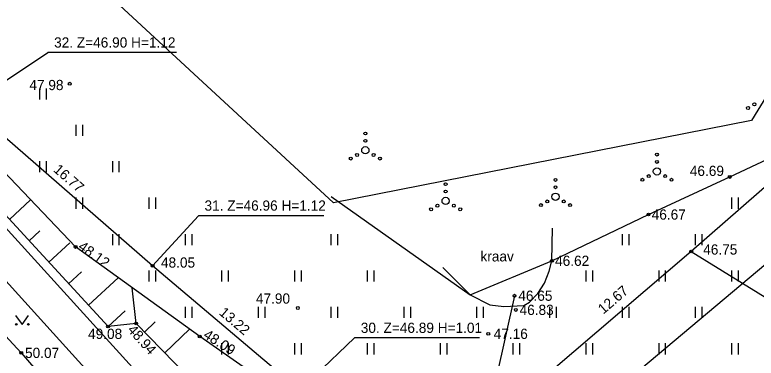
# Model space of a CAD drawing. Extents: x 642747 to 644424, y 6457048 to 6458238.
# Drawn here: x 644020.1 to 644071, y 6457560 to 6457583.6 of the extents above; entities that cross this region are included whole.
import ezdxf

# ---------------------------------------------------------------- set-up
doc = ezdxf.new("R2010")
doc.units = 0
for name, color, linetype in [('DTRASS', 7, 'Continuous'), ('HALJASTUS', 7, 'Continuous'), ('JOONSIDE', 7, 'Continuous'), ('KOORDPUNKT', 7, 'Continuous'), ('KORGUS', 7, 'Continuous'), ('KPKAABEL', 7, 'Continuous'), ('MOOTPIIR', 7, 'Continuous'), ('RELJEEF', 7, 'Continuous'), ('TEE', 7, 'Continuous'), ('VEEKOGU', 7, 'Continuous')]:
    doc.layers.add(name, color=color, linetype=linetype)

msp = doc.modelspace()

# ---------------------------------------------------------------- linework, layer by layer
at = {"layer": 'DTRASS'}
msp.add_lwpolyline([(644054.394, 6457564.336), (644048.175, 6457536.442)], dxfattribs=at)
at = {"layer": 'HALJASTUS'}
for p, q in [((644021.79, 6457578.569), (644021.79, 6457577.807)), ((644022.245, 6457578.569), (644022.245, 6457577.807)), ((644024.29, 6457576.069), (644024.29, 6457575.307)), ((644024.745, 6457576.069), (644024.745, 6457575.307)), ((644021.79, 6457573.569), (644021.79, 6457572.807)), ((644022.245, 6457573.569), (644022.245, 6457572.807)), ((644026.79, 6457573.569), (644026.79, 6457572.807)), ((644027.245, 6457573.569), (644027.245, 6457572.807)), ((644024.29, 6457571.069), (644024.29, 6457570.307)), ((644024.745, 6457571.069), (644024.745, 6457570.307)), ((644029.29, 6457571.069), (644029.29, 6457570.307)), ((644029.745, 6457571.069), (644029.745, 6457570.307)), ((644069.29, 6457571.069), (644069.29, 6457570.307)), ((644069.745, 6457571.069), (644069.745, 6457570.307)), ((644026.79, 6457568.569), (644026.79, 6457567.807)), ((644027.245, 6457568.569), (644027.245, 6457567.807)), ((644031.79, 6457568.569), (644031.79, 6457567.807)), ((644032.245, 6457568.569), (644032.245, 6457567.807)), ((644041.79, 6457568.569), (644041.79, 6457567.807)), ((644042.245, 6457568.569), (644042.245, 6457567.807)), ((644061.79, 6457568.569), (644061.79, 6457567.807)), ((644062.245, 6457568.569), (644062.245, 6457567.807)), ((644066.79, 6457568.569), (644066.79, 6457567.807)), ((644067.245, 6457568.569), (644067.245, 6457567.807)), ((644029.29, 6457566.069), (644029.29, 6457565.307)), ((644029.745, 6457566.069), (644029.745, 6457565.307)), ((644034.29, 6457566.069), (644034.29, 6457565.307)), ((644034.745, 6457566.069), (644034.745, 6457565.307)), ((644039.29, 6457566.069), (644039.29, 6457565.307)), ((644039.745, 6457566.069), (644039.745, 6457565.307)), ((644044.29, 6457566.069), (644044.29, 6457565.307)), ((644044.745, 6457566.069), (644044.745, 6457565.307)), ((644059.29, 6457566.069), (644059.29, 6457565.307)), ((644059.745, 6457566.069), (644059.745, 6457565.307)), ((644064.29, 6457566.069), (644064.29, 6457565.307)), ((644064.745, 6457566.069), (644064.745, 6457565.307)), ((644069.29, 6457566.069), (644069.29, 6457565.307)), ((644069.745, 6457566.069), (644069.745, 6457565.307)), ((644031.79, 6457563.569), (644031.79, 6457562.807)), ((644032.245, 6457563.569), (644032.245, 6457562.807)), ((644036.79, 6457563.569), (644036.79, 6457562.807)), ((644037.245, 6457563.569), (644037.245, 6457562.807)), ((644041.79, 6457563.569), (644041.79, 6457562.807)), ((644042.245, 6457563.569), (644042.245, 6457562.807)), ((644046.79, 6457563.569), (644046.79, 6457562.807)), ((644047.245, 6457563.569), (644047.245, 6457562.807)), ((644051.79, 6457563.569), (644051.79, 6457562.807)), ((644052.245, 6457563.569), (644052.245, 6457562.807)), ((644056.79, 6457563.569), (644056.79, 6457562.807)), ((644057.245, 6457563.569), (644057.245, 6457562.807)), ((644061.79, 6457563.569), (644061.79, 6457562.807)), ((644062.245, 6457563.569), (644062.245, 6457562.807)), ((644066.79, 6457563.569), (644066.79, 6457562.807)), ((644067.245, 6457563.569), (644067.245, 6457562.807)), ((644020.133, 6457562.977), (644020.597, 6457562.37)), ((644020.597, 6457562.37), (644021.042, 6457562.977)), ((644034.29, 6457561.069), (644034.29, 6457560.307)), ((644034.745, 6457561.069), (644034.745, 6457560.307)), ((644039.29, 6457561.069), (644039.29, 6457560.307)), ((644039.745, 6457561.069), (644039.745, 6457560.307)), ((644044.29, 6457561.069), (644044.29, 6457560.307)), ((644044.745, 6457561.069), (644044.745, 6457560.307)), ((644049.29, 6457561.069), (644049.29, 6457560.307)), ((644049.745, 6457561.069), (644049.745, 6457560.307)), ((644054.29, 6457561.069), (644054.29, 6457560.307)), ((644054.745, 6457561.069), (644054.745, 6457560.307)), ((644059.29, 6457561.069), (644059.29, 6457560.307)), ((644059.745, 6457561.069), (644059.745, 6457560.307)), ((644064.29, 6457561.069), (644064.29, 6457560.307)), ((644064.745, 6457561.069), (644064.745, 6457560.307)), ((644069.29, 6457561.069), (644069.29, 6457560.307)), ((644069.745, 6457561.069), (644069.745, 6457560.307))]:
    msp.add_line(p, q, dxfattribs=at)
for points in [[(643947.897, 6457637.828), (643981.209, 6457604.157), (643998.602, 6457584.178), (644020.537, 6457560.412), (644029.925, 6457549.512)], [(644041.809, 6457571.148), (644051.359, 6457564.407), (644056.959, 6457566.734), (644063.59, 6457569.91), (644069.17, 6457572.488), (644076.19, 6457575.794), (644080.356, 6457579.056), (644082.641, 6457584.464), (644086.464, 6457590.743), (644093.515, 6457598.78), (644095.215, 6457603.14), (644095.047, 6457607.095)]]:
    msp.add_lwpolyline(points, dxfattribs=at)
for centre, radius in [((644070.857, 6457577.474), 0.1), ((644070.422, 6457577.224), 0.1), ((644044.155, 6457575.471), 0.1), ((644044.155, 6457574.971), 0.1), ((644044.155, 6457574.321), 0.25), ((644043.59, 6457573.996), 0.1), ((644044.72, 6457573.996), 0.1), ((644064.17, 6457574.021), 0.1), ((644043.155, 6457573.746), 0.1), ((644045.155, 6457573.746), 0.1), ((644064.17, 6457573.521), 0.1), ((644064.17, 6457572.871), 0.25), ((644057.208, 6457572.282), 0.1), ((644063.17, 6457572.296), 0.1), ((644063.605, 6457572.546), 0.1), ((644064.735, 6457572.546), 0.1), ((644065.17, 6457572.296), 0.1), ((644049.667, 6457571.992), 0.1), ((644057.208, 6457571.782), 0.1), ((644049.667, 6457571.492), 0.1), ((644057.208, 6457571.132), 0.25), ((644049.667, 6457570.842), 0.25), ((644056.643, 6457570.807), 0.1), ((644057.773, 6457570.807), 0.1), ((644048.667, 6457570.267), 0.1), ((644049.102, 6457570.517), 0.1), ((644050.232, 6457570.517), 0.1), ((644050.667, 6457570.267), 0.1), ((644056.208, 6457570.557), 0.1), ((644058.208, 6457570.557), 0.1), ((644020.196, 6457562.37), 0.055), ((644021.025, 6457562.37), 0.055)]:
    msp.add_circle(centre, radius, dxfattribs=at)
at = {"layer": 'KOORDPUNKT'}
for p, q in [((644016.901, 6457577.396), (644022.373, 6457581.022)), ((644031.192, 6457581.022), (644022.373, 6457581.022)), ((644029.553, 6457566.384), (644032.696, 6457569.824)), ((644041.306, 6457569.824), (644032.696, 6457569.824)), ((644066.524, 6457567.369), (644072.19, 6457563.871)), ((644039.639, 6457557.844), (644043.422, 6457561.433)), ((644051.996, 6457561.433), (644043.422, 6457561.433))]:
    msp.add_line(p, q, dxfattribs=at)
for points in [[(644066.524, 6457567.369), (644066.524, 6457567.369), (644066.524, 6457567.369)], [(644029.553, 6457566.384), (644029.553, 6457566.384), (644029.553, 6457566.384)]]:
    msp.add_lwpolyline(points, dxfattribs=at)
at = {"layer": 'KORGUS'}
for centre in [(644023.863, 6457578.887), (644069.17, 6457572.488), (644063.59, 6457569.91), (644024.267, 6457567.686), (644066.524, 6457567.369), (644056.959, 6457566.734), (644029.553, 6457566.384), (644054.394, 6457564.336), (644039.519, 6457563.493), (644054.482, 6457563.363), (644026.5, 6457562.219), (644028.426, 6457562.43), (644052.59, 6457561.721), (644032.787, 6457561.533), (644020.537, 6457560.412)]:
    msp.add_circle(centre, 0.1, dxfattribs=at)
at = {"layer": 'KPKAABEL'}
msp.add_lwpolyline([(644103.079, 6457652.715), (644111.131, 6457630.665), (644117.872, 6457612.305), (644117.831, 6457611.89), (644117.527, 6457611.592), (644112.751, 6457607.616), (644102.693, 6457600.124), (644092.698, 6457590.582), (644078.192, 6457577.561), (644066.524, 6457567.369), (644056.896, 6457559.139), (644048.865, 6457552.537), (644048.039, 6457551.927), (644047.155, 6457551.979), (644039.639, 6457557.844), (644029.553, 6457566.384), (644016.901, 6457577.396), (644002.145, 6457590.823), (643989.718, 6457602.415), (643976.894, 6457615.305), (643965.556, 6457626.702)], dxfattribs=at)
at = {"layer": 'MOOTPIIR'}
msp.add_lwpolyline([(643525.446, 6457467.559), (643537.447, 6457435.458), (643944.848, 6457628.51), (644046.626, 6457529.09), (644067.022, 6457529.09), (644138.408, 6457598.401), (644075.1, 6457775.215), (644046.02, 6457752.582), (644092.466, 6457611.94), (644070.657, 6457576.375), (644041.981, 6457570.717), (643942.223, 6457662.862)], close=True, dxfattribs=at)
at = {"layer": 'RELJEEF'}
for p, q in [((644019.726, 6457569.575), (644021.183, 6457570.917)), ((644021.081, 6457568.103), (644021.823, 6457568.787)), ((644022.436, 6457566.632), (644023.882, 6457567.964)), ((644023.791, 6457565.161), (644024.664, 6457565.965)), ((644025.146, 6457563.69), (644027.191, 6457565.574)), ((644028.426, 6457562.43), (644028.158, 6457564.876)), ((644026.5, 6457562.219), (644027.673, 6457563.299)), ((644029.003, 6457561.837), (644029.72, 6457562.534)), ((644030.398, 6457560.403), (644032.083, 6457562.042))]:
    msp.add_line(p, q, dxfattribs=at)
for points in [[(644040.652, 6457556.032), (644032.787, 6457561.533), (644024.267, 6457567.686), (644013.888, 6457578.559), (644004.095, 6457588.275), (643993.471, 6457598.922), (643984.908, 6457608.291), (643982.871, 6457611.083), (643985.277, 6457614.077)], [(644038.518, 6457554.209), (644034.582, 6457556.103), (644028.426, 6457562.43), (644026.5, 6457562.219), (644014.667, 6457575.068), (644002.176, 6457588.096), (643989.067, 6457601.802), (643980.842, 6457610.819), (643983.167, 6457613.454)]]:
    msp.add_lwpolyline(points, dxfattribs=at)
at = {"layer": 'TEE'}
for points in [[(644045.414, 6457537.961), (644044.12, 6457540.285), (644037.139, 6457549.214), (644032.867, 6457554.025), (644030.182, 6457557.185), (644018.058, 6457570.518), (644006.462, 6457582.723), (643994.161, 6457595.954), (643981.396, 6457609.563), (643968.526, 6457623.391), (643955.996, 6457636.272), (643954.769, 6457637.545)], [(643953.164, 6457635.53), (643954.521, 6457634.202), (643966.746, 6457621.258), (643979.497, 6457607.902), (643992.403, 6457593.942), (644004.789, 6457581.012), (644016.437, 6457568.699), (644028.361, 6457555.547), (644031.31, 6457552.113), (644035.03, 6457547.601), (644042.186, 6457538.294), (644042.986, 6457534.354), (644042.17, 6457531.304), (644041.041, 6457530.634)], [(644051.619, 6457549.694), (644075.076, 6457569.399), (644100.273, 6457592.468), (644111.741, 6457604.69), (644121.185, 6457609.883)]]:
    msp.add_lwpolyline(points, dxfattribs=at)
at = {"layer": 'VEEKOGU'}
for points in [[(644051.359, 6457564.407), (644052.694, 6457563.714), (644053.665, 6457563.59), (644055.044, 6457563.668), (644055.415, 6457563.901), (644055.986, 6457564.498), (644056.462, 6457565.204), (644056.764, 6457566.017), (644056.959, 6457566.734), (644056.998, 6457568.981)], [(644051.359, 6457564.407), (644049.478, 6457566.264)]]:
    msp.add_lwpolyline(points, dxfattribs=at)

# ---------------------------------------------------------------- texts
at = {"layer": 'JOONSIDE'}
for s, rotation, p in [('16.77', 318.9645, (644022.696, 6457572.906)), ('12.67', 40.5238, (644060.491, 6457563.037)), ('13.22', 319.7448, (644034.065, 6457563.088))]:
    msp.add_text(s, height=0.7, rotation=rotation, dxfattribs=at).set_placement(p)
at = {"layer": 'KOORDPUNKT'}
for s, p in [('32. Z=46.90 H=1.12', (644022.793, 6457581.372)), ('31. Z=46.96 H=1.12', (644033.116, 6457570.174)), ('30. Z=46.89 H=1.01', (644043.842, 6457561.783))]:
    msp.add_text(s, height=0.7, dxfattribs=at).set_placement(p)
at = {"layer": 'KORGUS'}
for s, p in [(' 47.98', (644020.834, 6457578.451)), ('46.69', (644066.428, 6457572.558)), ('46.67', (644063.811, 6457569.56)), ('46.75', (644067.346, 6457567.159)), ('48.05', (644030.128, 6457566.264)), ('46.62', (644057.18, 6457566.384)), (' 46.65', (644054.394, 6457563.986)), (' 47.90', (644036.384, 6457563.792)), (' 46.83', (644054.482, 6457563.013)), (' 49.08', (644024.863, 6457561.37)), ('47.16', (644052.965, 6457561.371)), (' 50.07', (644020.537, 6457560.062))]:
    msp.add_text(s, height=0.7, dxfattribs=at).set_placement(p)
for s, rotation, p in [(' 48.12', 324.1867, (644024.173, 6457567.726)), (' 48.94', 311.8035, (644027.613, 6457562.157)), (' 48.09', 327.2731, (644032.758, 6457561.627))]:
    msp.add_text(s, height=0.7, rotation=rotation, dxfattribs=at).set_placement(p)
at = {"layer": 'VEEKOGU'}
msp.add_text('kraav', height=0.7, dxfattribs=at).set_placement((644052.058, 6457566.689))

doc.saveas('drawing.dxf')
